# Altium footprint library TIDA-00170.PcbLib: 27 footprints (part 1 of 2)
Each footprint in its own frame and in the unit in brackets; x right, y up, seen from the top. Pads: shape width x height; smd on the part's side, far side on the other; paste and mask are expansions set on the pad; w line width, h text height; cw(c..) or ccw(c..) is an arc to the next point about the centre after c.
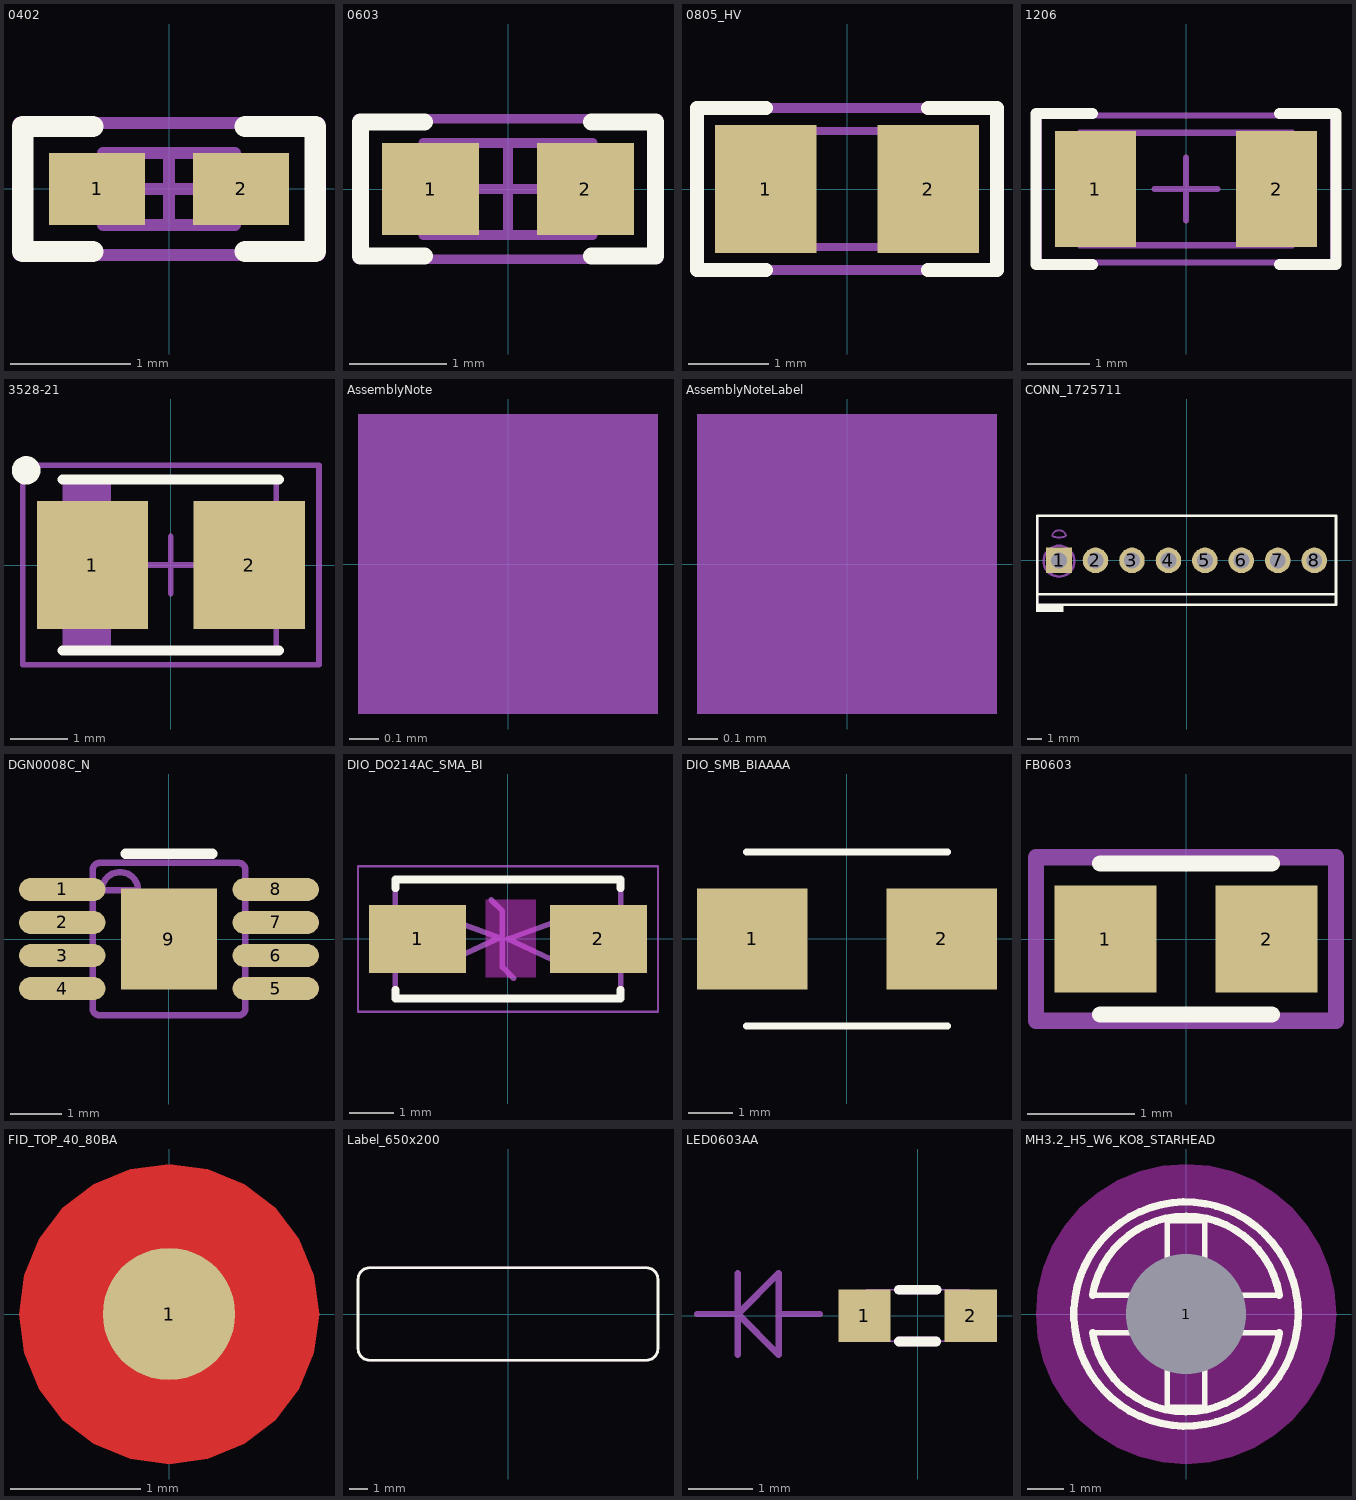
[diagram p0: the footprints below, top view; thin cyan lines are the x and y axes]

## 0402 [mm] "0402 from SM-752 data"
height 0.6
pads (2):
  rect 0.8x0.6 smd: 1(-0.6,0) 2(0.6,0)
Top Overlay:
  lines w0.178: -0.635,-0.521 -1.219,-0.521 -1.219,0.521 -0.635,0.521 ; 0.635,-0.521 1.219,-0.521 1.219,0.521 0.635,0.521
Mechanical 5:
  lines w0.1: -1.25,-0.55 -1.25,0.55 1.25,0.55 1.25,-0.55 -1.25,-0.55
  text ".Designator" at -1.117,-0.305 h0.61
Mechanical 13:
  lines w0.1: -0.35,-0.3 -0.35,0.3 ; 0.35,-0.3 0.35,0.3 ; -0.55,-0.3 0.55,-0.3 0.55,0.3 -0.55,0.3 -0.55,-0.3
Mechanical 15:
  lines w0.1: -0.3,0 0.3,0 ; 0,-0.3 0,0.3 ; -1.25,-0.55 1.25,-0.55 1.25,0.55 -1.25,0.55 -1.25,-0.55
3D body: height 0.6, standoff 0, extent 0.351,-0.299 0.549,0.299
3D body: height 0.6, standoff 0, extent -0.349,-0.299 0.349,0.299
3D body: height 0.6, standoff 0, extent -0.549,-0.299 -0.351,0.299

## 0603 [mm] "0603 from SM-752 data"
height 0.85
pads (2):
  rect 1x0.95 smd: 1(-0.8,0) 2(0.8,0)
Top Overlay:
  lines w0.178: -0.864,-0.691 -1.524,-0.691 -1.524,0.693 -0.864,0.693 ; 0.864,-0.691 1.524,-0.691 1.524,0.693 0.864,0.693
Mechanical 5:
  lines w0.1: -1.55,-0.725 1.55,-0.725 1.55,0.725 -1.55,0.725 -1.55,-0.725
  text ".Designator" at -1.397,-0.381 h0.76
Mechanical 13:
  lines w0.1: -0.55,-0.475 -0.55,0.475 ; 0.55,-0.475 0.55,0.475 ; -0.875,-0.475 -0.875,0.475 0.875,0.475 0.875,-0.475 -0.875,-0.475
Mechanical 15:
  lines w0.1: -0.475,0 0.475,0 ; 0,-0.475 0,0.475 ; -1.55,-0.725 -1.55,0.725 1.55,0.725 1.55,-0.725 -1.55,-0.725
3D body: height 0.85, standoff 0, extent 0.551,-0.474 0.874,0.474
3D body: height 0.85, standoff 0, extent -0.549,-0.474 0.549,0.474
3D body: height 0.85, standoff 0, extent -0.874,-0.474 -0.551,0.474

## 0805_HV [mil] "0805 with 30mil clearance between pads"
height 43.31
pads (2):
  rect 50x63 smd: 1(-40,0) 2(40,0)
Top Overlay:
  lines w7: -40,-40 -74,-40 -74,0 -74,40 -40,40 ; 40,-40 74,-40 74,0 74,40 40,40
Mechanical 5:
  lines w5: -74,-40 74,-40 74,40 -74,40 -74,-40
  text ".Designator" at -64,-17 h35
Mechanical 13:
  lines w3.94: -25.59,-28.54 -25.59,28.54 ; 25.59,-28.54 25.59,28.54 ; -43.31,-28.54 -43.31,28.54 43.31,28.54 43.31,-28.54 -43.31,-28.54
3D body: height 43.31, standoff 0, extent 25.61,-28.52 43.29,28.52
3D body: height 43.31, standoff 0, extent -25.57,-28.52 25.57,28.52
3D body: height 43.31, standoff 0, extent -43.29,-28.52 -25.61,28.52

## 1206 [mm] "1206 from SM-752 data"
height 1.35
pads (2):
  rect 1.3x1.85 smd: 1(-1.45,0) 2(1.45,0)
Top Overlay:
  lines w0.178: -1.5,-1.21 -2.4,-1.21 -2.4,1.21 -1.5,1.21 ; 1.5,-1.21 2.4,-1.21 2.4,1.21 1.5,1.21
Mechanical 5:
  lines w0.1: -1.7,-0.9 1.7,-0.9 1.7,0.9 -1.7,0.9 -1.7,-0.9
  text ".Designator" at -1.475,-0.4 h0.81
Mechanical 13:
  lines w0.1: -1.2,-0.9 -1.2,0.9 ; 1.2,-0.9 1.2,0.9 ; -1.7,-0.9 1.7,-0.9 1.7,0.9 -1.7,0.9 -1.7,-0.9
Mechanical 15:
  lines w0.1: -0.5,0 0.5,0 ; 0,-0.5 0,0.5 ; -2.35,-1.175 2.35,-1.175 2.35,1.175 -2.35,1.175 -2.35,-1.175
3D body: height 1.35, standoff 0, extent -1.699,-0.899 -1.201,0.899
3D body: height 1.35, standoff 0, extent -1.199,-0.899 1.199,0.899
3D body: height 1.35, standoff 0, extent 1.201,-0.899 1.699,0.899

## 3528-21 [mm] "Medium Density IPC, based on SM-782 section 8.4"
height 2.1
pads (2):
  rect 1.95x2.25 smd: 1(-1.375,0) 2(1.375,0)
Top Overlay:
  circle w0.25: c-2.539,1.661 r0.125
  lines w0.178: -1.9,-1.5 1.9,-1.5 ; -1.9,1.5 1.9,1.5
Mechanical 5:
  rectangle: -1.85,-1.5 -1.1,1.5
  lines w0.1: -1.1,-1.5 -1.1,1.5 ; -1.85,-1.5 1.85,-1.5 1.85,1.5 -1.85,1.5 -1.85,-1.5
  text ".Designator" at -0.925,-0.35 h0.71
Mechanical 15:
  lines w0.1: -0.5,0 0.5,0 ; 0,-0.5 0,0.5 ; -2.6,-1.75 -2.6,1.75 2.6,1.75 2.6,-1.75 -2.6,-1.75
3D body: height 2.1, standoff 2.1, extent -1.849,-1.499 -1.101,1.499
3D body: height 2.1, standoff 0, extent -1.85,-1.5 1.85,1.5

## AssemblyNote [mm] "Assembly Note"
Mechanical 5:
  rectangle: -0.508,-0.508 0.508,0.508
  text ".Designator" at -4.191,-0.508 h0.76
  text ".Comment" at 1.143,-0.508 h0.76

## AssemblyNoteLabel [mm] "Assembly Note for PCB Labels"
Mechanical 5:
  rectangle: -0.508,-0.508 0.508,0.508
  text ".Designator" at -3.683,-0.457 h0.76
  text "Install label in silkscreened box after final wash.  Text shall be 8 pt font.  Text shall be per the Label Table in the PDF schematic." at 1.651,-0.457 h0.76

## CONN_1725711 [mm] "Phoenix Contact"
height 13.8
pads (8):
  rect 1.78x1.78 hole 1.1: 1(-8.89,0)
  round 1.78 hole 1.1: 2(-6.35,0) 3(-3.81,0) 4(-1.27,0) 5(1.27,0) 6(3.81,0) 7(6.35,0) 8(8.89,0)
Top Overlay:
  rectangle: -10.493,-3.6 -8.589,-3.1
  lines w0.178: -10.39,-2.361 10.39,-2.361 ; -10.404,-3.1 -10.398,3.1 10.4,3.1 10.4,-3.1 -10.404,-3.1
Mechanical 5:
  lines w0.127: -10.39,-2.361 10.39,-2.361 ; -10.39,-2.361 -10.39,-1.51 -10.39,-1.22 -10.39,1.132 -10.39,1.417 -10.39,3.1 10.39,3.1 10.39,1.417 10.39,1.132 10.39,-1.22 10.39,-1.51 10.39,-2.361 ; -10.39,-2.361 -10.39,-2.8 -10.39,-3.1 10.39,-3.1 10.39,-2.8 10.39,-2.361 ; -9.788,-0.594 ccw(c-8.89,-0.05) -9.434,-0.948 ; -9.788,-0.594 cw(c-8.89,-0.05) -8.89,1 cw(c-8.89,-0.05) -8.346,0.848 ; -9.788,-0.594 -9.4,-0.206 -8.89,0.304 -8.684,0.51 -8.346,0.848 ; -9.434,-0.948 ccw(c-8.89,-0.05) -8.89,-1.1 ccw(c-8.89,-0.05) -7.992,0.494 ; -9.434,-0.948 -9.021,-0.534 -8.89,-0.403 -8.356,0.131 -7.992,0.494 ; -8.346,0.848 cw(c-8.89,-0.05) -7.992,0.494 ; -9.365,1.741 -9.365,1.748 -9.365,1.755 -9.363,1.763 cw(c-8.89,1.6) -8.89,2.1 cw(c-8.89,1.6) -8.417,1.763 -8.415,1.751 -8.415,1.744 -8.416,1.737 -8.418,1.729 -8.421,1.722 -8.426,1.715 -8.432,1.708 -8.439,1.701 -8.447,1.694 -8.456,1.687 -8.466,1.68 -8.477,1.674 -8.49,1.668 -8.503,1.662 -8.517,1.656 -8.533,1.65 -8.549,1.645 -8.566,1.639 -8.584,1.635 -8.602,1.63 -8.621,1.626 -8.641,1.622 -8.662,1.618 -8.683,1.615 -8.705,1.612 -8.727,1.609 -8.749,1.607 -8.772,1.605 -8.795,1.603 -8.819,1.602 -8.842,1.601 -8.866,1.6 -8.89,1.6 -8.926,1.6 -8.95,1.601 -8.973,1.602 -8.997,1.604 -9.02,1.606 -9.042,1.608 -9.065,1.61 -9.087,1.613 -9.108,1.616 -9.129,1.62 -9.149,1.624 -9.169,1.628 -9.188,1.632 -9.206,1.637 -9.223,1.642 -9.24,1.647 -9.255,1.653 -9.27,1.659 -9.284,1.665 -9.297,1.671 -9.309,1.677 -9.319,1.684 -9.329,1.691 -9.338,1.697 -9.345,1.704 -9.351,1.711 -9.357,1.719 -9.361,1.726 -9.363,1.733 -9.365,1.741 ; -8.89,-1.15 ccw(c-8.89,-0.05) -8.89,1.05 ccw(c-8.89,-0.05) -8.89,-1.15
  text ".Designator" at -4.7,-0.5 h1.52
3D body: height 8.52, standoff -3.48, extent -10.39,-3.1 10.39,3.1

## DGN0008C_N [mm] "TSOP, 8-Leads, Body 3x3mm, Pitch 0.65mm, Thermal Pad 1.98x1.88mm, IPC Medium Density"
height 1.1
pads (9):
  oval 1.7x0.45 smd mask+0.05: 1(-2.1,0.975) 2(-2.1,0.325) 3(-2.1,-0.325) 4(-2.1,-0.975) 5(2.1,-0.975) 6(2.1,-0.325) 7(2.1,0.325) 8(2.1,0.975)
  rect 1.88x1.98 smd mask+0.07: 9(0,0)
Top Overlay:
  lines w0.2: -0.85,1.675 0.85,1.675
Mechanical 5:
  lines w0.127: -2.45,-1.131 -2.21,-1.131 -2.09,-1.131 -2.087,-1.131 -1.784,-1.131 -1.498,-1.131 -1.498,-0.826 -1.784,-0.826 -2.087,-0.826 -2.09,-0.826 -2.21,-0.826 -2.45,-0.826 -2.45,-1.131 ; -2.45,-0.48 -2.21,-0.48 -2.09,-0.48 -2.087,-0.48 -1.784,-0.48 -1.498,-0.48 -1.498,-0.175 -1.784,-0.175 -2.087,-0.175 -2.09,-0.175 -2.21,-0.175 -2.45,-0.175 -2.45,-0.48 ; -2.45,0.17 -2.21,0.17 -2.09,0.17 -2.087,0.17 -1.784,0.17 -1.498,0.17 -1.498,0.475 -1.784,0.475 -2.087,0.475 -2.09,0.475 -2.21,0.475 -2.45,0.475 -2.45,0.17 ; -2.45,0.82 -2.21,0.82 -2.09,0.82 -2.087,0.82 -1.784,0.82 -1.498,0.82 -1.498,1.125 -1.784,1.125 -2.087,1.125 -2.09,1.125 -2.21,1.125 -2.45,1.125 -2.45,0.82 ; -1.497,-1.377 ccw(c-1.37,-1.374) -1.373,-1.501 -1.371,-1.501 1.373,-1.501 1.375,-1.501 ccw(c1.373,-1.374) 1.5,-1.377 1.5,-1.374 1.5,1.369 1.5,1.372 ccw(c1.373,1.369) 1.375,1.496 1.373,1.496 -1.371,1.496 -1.373,1.496 ccw(c-1.37,1.369) -1.497,1.372 -1.498,1.369 -1.498,-1.374 -1.497,-1.377 ; -1.32,0.962 cw(c-0.964,0.962) -0.609,0.962 -1.32,0.962 ; 1.5,-1.131 1.786,-1.131 2.089,-1.131 2.093,-1.131 2.213,-1.131 2.452,-1.131 2.452,-0.826 2.213,-0.826 2.093,-0.826 2.089,-0.826 1.786,-0.826 1.5,-0.826 1.5,-1.131 ; 1.5,-0.48 1.786,-0.48 2.089,-0.48 2.093,-0.48 2.213,-0.48 2.452,-0.48 2.452,-0.175 2.213,-0.175 2.093,-0.175 2.089,-0.175 1.786,-0.175 1.5,-0.175 1.5,-0.48 ; 1.5,0.17 1.786,0.17 2.089,0.17 2.093,0.17 2.213,0.17 2.452,0.17 2.452,0.475 2.213,0.475 2.093,0.475 2.089,0.475 1.786,0.475 1.5,0.475 1.5,0.17 ; 1.5,0.82 1.786,0.82 2.089,0.82 2.093,0.82 2.213,0.82 2.452,0.82 2.452,1.125 2.213,1.125 2.093,1.125 2.089,1.125 1.786,1.125 1.5,1.125 1.5,0.82
  text ".Designator" at -0.125,1.15 h0.64
Mechanical 15:
  lines w0.1: -0.5,0 0.5,0 ; 0,-0.5 0,0.5
3D body: height 0.94, standoff -0.02, extent -2.451,-1.499 2.451,1.498

## DIO_DO214AC_SMA_BI [mm] "DIODE, BIDIRECTIONAL, DO-214AC, 2-PIN"
height 2.29
pads (2):
  rect 2.2x1.55 smd: 1(-2.05,0) 2(2.05,0)
Top Layer keep-out:
  rectangle: -0.506,-0.869 0.637,0.891
Top Overlay:
  lines w0.178: -2.55,-1.15 -2.55,-1.35 2.55,-1.35 2.55,-1.15 ; -2.55,1.15 -2.55,1.35 2.55,1.35 2.55,1.15
  text ".Designator" at -1.015,1.937 h1.02
Mechanical 5:
  lines w0.127: -2.54,0 -1.415,0 ; -1.397,-0.504 -1.397,0.468 -0.191,0.029 -1.353,-0.513 ; -0.381,0.889 -0.127,0.635 -0.127,-0.635 0.127,-0.889 ; 1.161,-0.542 0,0 1.206,0.438 1.206,-0.533 ; 1.27,0 2.395,0 ; -2.552,-1.332 2.552,-1.332 2.552,1.332 -2.552,1.332 ; -2.552,-1.332 -2.552,1.332 ; -2.552,-1.332 -2.552,1.332
  text ".Designator" at -1.524,-0.508 h1.02
Mechanical 15:
  lines w0.05: -3.4,-1.65 3.4,-1.65 3.4,1.65 -3.4,1.65 -3.4,-1.65
Mechanical 17:
  text "FOOTPRINT FOR BI-DIRECTIONAL USE ONLY" at -7,-0.029 h0.5
3D body: height 2.29, standoff 0, extent -2.552,-1.332 2.552,1.332

## DIO_SMB_BIAAAA [mm]
height 2.28
pads (2):
  rect 2.5x2.3 smd: 1(-2.15,0) 2(2.15,0)
Top Overlay:
  lines w0.152: -2.285,-1.97 2.285,-1.97 ; -2.285,1.97 2.285,1.97
Mechanical 15:
  lines w0.025: -2.285,-1.97 2.285,-1.97 ; -2.285,1.97 2.285,1.97

## FB0603 [mm]
height 3
pads (2):
  rect 0.95x1 smd: 1(-0.75,0) 2(0.75,0)
Top Overlay:
  lines w0.152: -0.8,-0.703 0.8,-0.703 ; -0.8,0.703 0.8,0.703
Mechanical 5:
  lines w0.152: -1.397,-0.762 -1.397,0.762 1.397,0.762 1.397,0.127 1.397,-0.762 -1.397,-0.762
  text ".designator" at -1.143,-0.381 h0.76
Mechanical 15:
  lines w0.025: -0.8,-0.4 -0.8,0.4 ; 0.8,-0.4 0.8,0.4
  lines w0.1: -0.8,-0.4 -0.8,0.4

## FID_TOP_40_80BA [mil]
pads (1):
  round 40 smd mask+20: 1(0,0)
Top Layer:
  region: 45.39,0 43.84,11.75 39.31,22.69 32.09,32.09 22.69,39.31 11.75,43.84 0,45.39 -11.75,43.84 -22.69,39.31 -32.09,32.09 -39.31,22.69 -43.84,11.75 -45.39,0 -43.84,-11.75 -39.31,-22.69 -32.09,-32.09 -22.69,-39.31 -11.75,-43.84 0,-45.39 11.75,-43.84 22.69,-39.31 32.09,-32.09 39.31,-22.69 43.84,-11.75

## Label_650x200 [mm] "Thermal Transfer Label"
height 0.025
Top Overlay:
  lines w0.152: -8.255,-1.905 ccw(c-7.62,-1.905) -7.62,-2.54 7.62,-2.54 ccw(c7.62,-1.905) 8.255,-1.905 8.255,1.905 ccw(c7.62,1.905) 7.62,2.54 -7.62,2.54 ccw(c-7.62,1.905) -8.255,1.905 -8.255,-1.905
Mechanical 5:
  lines w0.127: -8.255,-1.905 ccw(c-7.62,-1.905) -7.62,-2.54 7.62,-2.54 ccw(c7.62,-1.905) 8.255,-1.905 8.255,1.905 ccw(c7.62,1.905) 7.62,2.54 -7.62,2.54 ccw(c-7.62,1.905) -8.255,1.905 -8.255,-1.905
  text ".Designator" at -1.524,-0.508 h0.76
3D body: height 0.03, standoff 0, extent -8.268,-2.553 8.268,2.553

## LED0603AA [mil]
height 35.43
pads (2):
  rect 32x32 smd: 1(-32.48,0) 2(32.48,0)
Top Overlay:
  lines w6: -11.42,-15.75 11.42,-15.75 ; -11.42,15.75 11.42,15.75
Mechanical 5:
  lines w6: -11.42,-15.75 11.42,-15.75 ; -11.42,15.75 11.42,15.75
  text ".Designator" at -140,-110 h60
Mechanical 15:
  lines w1: -31.5,-15.75 31.5,-15.75 31.5,15.75 -31.5,15.75 -31.5,-15.75
  lines w3.94: -134.79,0.96 -109.79,0.96 ; -109.79,-24.04 -109.79,25.96 ; -84.79,0.96 -59.79,0.96 ; -109.79,0.96 -84.79,25.96 -84.79,-24.04 -109.79,0.96

## MH3.2_H5_W6_KO8_STARHEAD [mil]
height 80
pads (1):
  round 20 / inner round 142 / far side round 20 hole 128 unplated mask+65: 1(0,0)
Top Overlay:
  circle w8: c0,0 r120
  lines w6: -100,-20 -20,-20 -20,-100 20,-100 20,-20 100,-20 ; -100,20 -20,20 -20,100 20,100 20,20 100,20
  lines w8: -100.02,-19.91 ccw(c0,-3.35) 99.99,-20.08 ; -99.99,20.09 cw(c0,3.36) 100.02,19.92
Keep-Out Layer:
  region: 160.49,0 158.52,25.11 152.64,49.6 143,72.86 129.84,94.34 113.49,113.49 94.34,129.84 72.86,143 49.6,152.64 25.11,158.52 0,160.49 -25.11,158.52 -49.6,152.64 -72.86,143 -94.34,129.84 -113.49,113.49 -129.84,94.34 -143,72.86 -152.64,49.6 -158.52,25.11 -160.49,0 -158.52,-25.11 -152.64,-49.6 -143,-72.86 -129.84,-94.34 -113.49,-113.49 -94.34,-129.84 -72.86,-143 -49.6,-152.64 -25.11,-158.52 0,-160.49 25.11,-158.52 49.6,-152.64 72.86,-143 94.34,-129.84 113.49,-113.49 129.84,-94.34 143,-72.86 152.64,-49.6 158.52,-25.11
